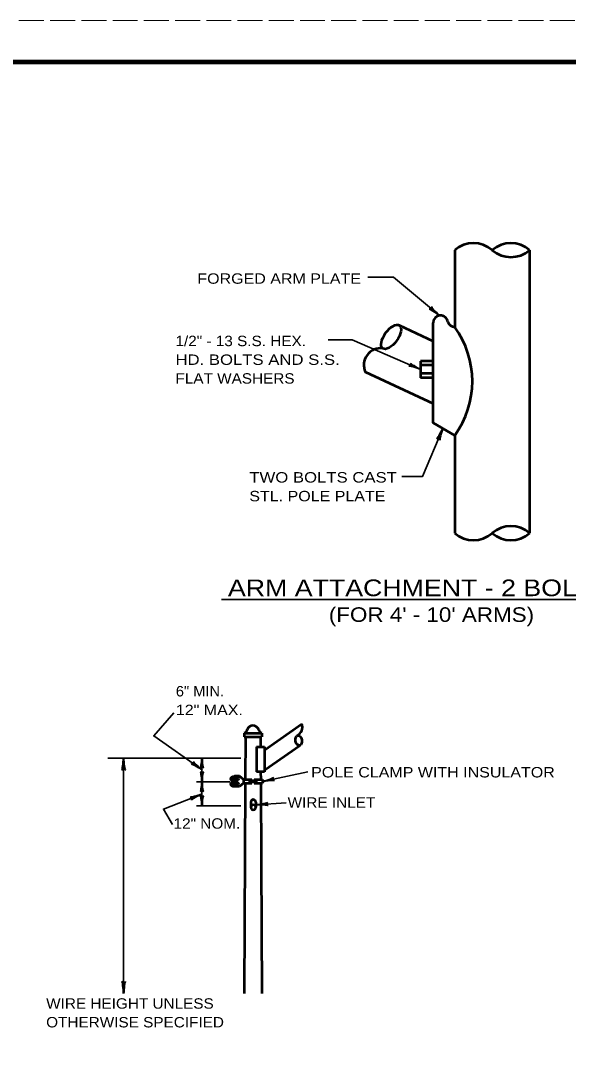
# Model space of a CAD drawing. Extents: x -1 to 679, y -228 to 440.
# Drawn here: x 224.4 to 356, y 192.8 to 440.2 of the extents above; entities that cross this region are included whole.
import ezdxf
from ezdxf.enums import TextEntityAlignment as Align

# ---------------------------------------------------------------- set-up
doc = ezdxf.new("R2010")
doc.units = 0
doc.linetypes.add('LONG_DASHED', pattern=[7.5, 6, -1.5])
doc.layers.add('1', color=7, linetype='Continuous', lineweight=35)
doc.layers.add('61', color=7, linetype='Continuous', lineweight=35)

msp = doc.modelspace()

# ---------------------------------------------------------------- hatches: boundary and pattern name
at = {"layer": '1'}
h = msp.add_hatch(color=256, dxfattribs=at)
edge = h.paths.add_edge_path()
edge.add_ellipse((275.808, 258.088), major_axis=(0.907, 0), ratio=0.6666667, start_angle=0, end_angle=360)
h = msp.add_hatch(color=256, dxfattribs=at)
edge = h.paths.add_edge_path()
edge.add_ellipse((275.808, 256.835), major_axis=(0.907, 0), ratio=0.6666667, start_angle=0, end_angle=360)

# ---------------------------------------------------------------- linework, layer by layer
at = {"layer": '1', "lineweight": 53}
for p, q in [((328.678, 385.1), (328.678, 366.6)), ((346.678, 385.1), (346.678, 317.1)), ((323.561, 363.183), (315.404, 366.986)), ((323.482, 358.445), (320.482, 358.445)), ((320.482, 358.445), (320.482, 354.445)), ((323.482, 357.445), (320.482, 357.445)), ((323.561, 348.183), (307.247, 355.79)), ((323.482, 355.445), (320.482, 355.445)), ((323.482, 354.445), (320.482, 354.445)), ((328.678, 340.6), (328.678, 317.1)), ((283.035, 265.061), (291.955, 271.301)), ((278.1, 269.095), (282.32, 269.095)), ((278.1, 269.095), (278.1, 268.195)), ((278.1, 268.195), (282.32, 268.195)), ((278.4, 268.195), (278.34, 257.915)), ((282.02, 268.195), (282.04, 265.775)), ((282.32, 269.095), (282.32, 268.195)), ((281.11, 265.775), (283.01, 265.775)), ((281.11, 265.775), (281.11, 259.735)), ((283.01, 265.775), (283.01, 259.735)), ((283.035, 260.221), (291.475, 266.121)), ((277.02, 258.695), (275.8, 258.695)), ((277.94, 257.915), (277.02, 258.695)), ((277.94, 257.915), (279.92, 257.915)), ((277.94, 257.915), (277.94, 257.015)), ((279.42, 257.915), (279.42, 257.015)), ((279.92, 257.915), (279.92, 257.015)), ((280.52, 257.915), (282.48, 257.915)), ((280.52, 257.915), (280.52, 257.015)), ((281, 257.915), (281, 257.015)), ((283.01, 259.735), (281.11, 259.735)), ((282.06, 259.735), (282.08, 257.915)), ((282.48, 257.915), (282.48, 257.015)), ((277.02, 256.235), (275.8, 256.235)), ((277.94, 257.015), (277.02, 256.235)), ((277.94, 257.015), (279.92, 257.015)), ((278.34, 257.015), (278.1, 206.515)), ((280.52, 257.015), (282.48, 257.015)), ((282.08, 257.015), (282.168, 237.955)), ((279.68, 252.455), (279.7, 251.255)), ((280.9, 252.475), (280.9, 251.255)), ((282.18, 237.955), (282.32, 206.515))]:
    msp.add_line(p, q, dxfattribs=at)
at = {"layer": '1'}
for p, q in [((272.629, 301.175), (367.649, 301.175)), ((245.329, 263.089), (277.329, 263.089)), ((249.145, 263.089), (249.145, 206.515)), ((267.971, 257.404), (267.971, 263.089)), ((282.509, 257.449), (293.413, 259.808)), ((266.657, 257.404), (274.657, 257.404)), ((267.971, 257.404), (267.971, 251.593)), ((280.94, 251.88), (288.21, 252.352)), ((266.657, 251.593), (277.329, 251.593))]:
    msp.add_line(p, q, dxfattribs=at)
for points in [[(325.01, 369.374), (313.992, 378.629), (307.832, 378.629)], [(320.482, 356.445), (304.054, 363.511), (298.304, 363.511)], [(325.826, 342.247), (320.974, 330.729), (315.963, 330.729)], [(268.019, 260.256), (256.395, 268.416), (261.221, 273.923)], [(267.951, 254.408), (258.706, 250.804), (260.882, 247.133)]]:
    msp.add_lwpolyline(points, dxfattribs=at)
at = {"layer": '1', "lineweight": 53}
msp.add_lwpolyline([(328.678, 340.6), (323.482, 343.6), (323.482, 367.6)], dxfattribs=at)
for centre, radius, start, end in [((333.178, 379.861), 6.907, 49.34186, 130.65814), ((342.178, 379.861), 6.907, 49.34186, 130.65814), ((342.178, 390.332), 6.907, 229.34186, 310.65814), ((325.269, 367.606), 1.787, 7.93348, 180.19616), ((328.793, 368.449), 1.852, 198.77174, 266.46102), ((310.949, 353.6), 21.985, 323.74899, 36.25101), ((310.874, 357.511), 4.015, 82.46091, 205.39139), ((333.178, 322.34), 6.907, 229.34186, 310.65814), ((342.178, 311.869), 6.907, 49.34186, 130.65814), ((342.178, 322.34), 6.907, 229.34186, 310.65814), ((277.902, 270.019), 0.936, 281.94387, 347.91984), ((280.213, 269.418), 1.453, 16.19781, 163.80219), ((282.523, 270.019), 0.936, 192.08016, 258.05613), ((289.835, 270.525), 2.264, 295.32486, 20.09191), ((280.289, 252.478), 0.605, 358.85054, 181.71286), ((280.295, 251.269), 0.605, 358.85054, 181.71286), ((280.295, 251.232), 0.605, 178.28714, 1.14946)]:
    msp.add_arc(centre, radius, start, end, dxfattribs=at)
at = {"layer": '1', "lineweight": 40}
for centre, major_axis, ratio, start_param, end_param in [((324.288, 370.257), (-1.232, 1.264), 0.07063, 6.2823074, 8.5597026), ((324.288, 370.257), (-1.232, 1.264), 0.07063, 6.2823074, 8.5597026), ((323.997, 369.865), (1.468, -1.029), 0.122415, 0.8963533, 3.1415927), ((323.997, 369.865), (1.468, -1.029), 0.122415, 0.8963533, 3.1415927), ((319.371, 356.622), (1.702, -0.562), 0.122415, 0.8963533, 3.1415927), ((319.371, 356.622), (1.702, -0.562), 0.122415, 0.8963533, 3.1415927), ((319.536, 357.082), (1.544, -0.855), 0.07063, 3.1407148, 5.41811), ((319.536, 357.082), (1.544, -0.855), 0.07063, 3.1407148, 5.41811), ((325.196, 341.297), (-0.844, -1.55), 0.07063, 6.2823074, 8.5597026), ((325.196, 341.297), (-0.844, -1.55), 0.07063, 6.2823074, 8.5597026), ((325.657, 341.134), (0.549, 1.706), 0.122415, 0.8963533, 3.1415927), ((325.657, 341.134), (0.549, 1.706), 0.122415, 0.8963533, 3.1415927), ((248.933, 261.968), (0.176, 1.756), 0.07063, 3.1407148, 5.41811), ((249.421, 261.998), (-0.156, 1.786), 0.122415, 0.8963533, 3.1415927), ((267.763, 261.959), (0.176, 1.756), 0.07063, 4.6265008, 5.41811), ((268.251, 261.989), (-0.156, 1.786), 0.122415, 0.8963533, 1.6612166), ((266.967, 260.657), (1.551, -0.898), 0.122415, 0.8963533, 3.1415927), ((266.967, 260.657), (1.551, -0.898), 0.122415, 0.8963533, 3.1415927), ((267.223, 261.073), (-1.337, 1.153), 0.07063, 6.2823074, 8.5597026), ((267.223, 261.073), (-1.337, 1.153), 0.07063, 6.2823074, 8.5597026), ((267.82, 262.451), (0.176, 1.756), 0.07063, 3.1407148, 4.3375003), ((267.82, 258.043), (0.176, -1.756), 0.07063, 1.9456851, 3.1424706), ((268.191, 262.498), (-0.156, 1.786), 0.122415, 1.9568509, 3.1415927), ((268.191, 257.995), (-0.156, -1.786), 0.122415, 3.1415927, 4.3263344), ((267.763, 258.534), (0.176, -1.756), 0.07063, 0.8650754, 1.6566845), ((267.763, 256.275), (0.176, 1.756), 0.07063, 4.6265008, 5.41811), ((268.251, 258.505), (-0.156, -1.786), 0.122415, 4.6219687, 5.386832), ((268.251, 256.304), (-0.156, 1.786), 0.122415, 0.8963533, 1.6612166), ((283.517, 257.95), (-1.712, -0.53), 0.122415, 0.8963533, 3.1415927), ((283.517, 257.95), (-1.712, -0.53), 0.122415, 0.8963533, 3.1415927), ((283.649, 257.479), (1.754, 0.2), 0.07063, 6.2823074, 8.5597026), ((283.649, 257.479), (1.754, 0.2), 0.07063, 6.2823074, 8.5597026), ((267.82, 256.766), (0.176, 1.756), 0.07063, 3.1407148, 4.3375003), ((268.191, 256.814), (-0.156, 1.786), 0.122415, 1.9568509, 3.1415927), ((266.83, 254.199), (-1.7, -0.474), 0.07063, 6.2823074, 8.5597026), ((267.035, 253.755), (1.607, 0.794), 0.122415, 0.8963533, 3.1415927), ((267.82, 252.231), (0.176, -1.756), 0.07063, 1.9456851, 3.1424706), ((267.763, 252.723), (0.176, -1.756), 0.07063, 0.8650754, 1.6566845), ((268.251, 252.693), (-0.156, -1.786), 0.122415, 4.6219687, 5.386832), ((268.191, 252.184), (-0.156, -1.786), 0.122415, 3.1415927, 4.3263344), ((282.01, 252.227), (-1.772, -0.272), 0.122415, 0.8963533, 3.1415927), ((282.071, 251.742), (-1.764, 0.061), 0.07063, 3.1407148, 5.41811), ((248.869, 207.606), (0.156, -1.786), 0.122415, 0.8963533, 3.1415927), ((248.869, 207.606), (0.156, -1.786), 0.122415, 0.8963533, 3.1415927), ((249.357, 207.636), (-0.176, -1.756), 0.07063, 3.1407148, 5.41811), ((249.357, 207.636), (-0.176, -1.756), 0.07063, 3.1407148, 5.41811)]:
    msp.add_ellipse(centre, major_axis=major_axis, ratio=ratio, start_param=start_param, end_param=end_param, dxfattribs=at)
at = {"layer": '1', "lineweight": 53}
for centre, major_axis, ratio in [((313.402, 364.239), (-2.002, -2.748), 0.476726), ((291.195, 267.314), (-0.27, 1.196), 0.618585), ((275.808, 258.088), (0.907, 0), 0.666667), ((275.808, 256.835), (0.907, 0), 0.666667)]:
    msp.add_ellipse(centre, major_axis=major_axis, ratio=ratio, dxfattribs=at)
at = {"layer": '61', "linetype": 'LONG_DASHED', "lineweight": 13}
msp.add_line((-0.979, 440.237), (679.041, 440.237), dxfattribs=at)
at = {"layer": '61', "lineweight": 158}
msp.add_lwpolyline([(668.061, 430.237), (29.021, 430.237), (29.021, 10.217)], dxfattribs=at)

# ---------------------------------------------------------------- texts
at = {"layer": '1'}
for s, height, width, p in [('FORGED ARM PLATE', 2.5, 1.15, (266.864, 377.017)), ('1/2" - 13 S.S. HEX.', 2.5, 1.1, (261.607, 362.028)), ('HD. BOLTS AND S.S.', 2.5, 1.2, (261.607, 357.528)), ('FLAT WASHERS', 2.5, 1.1, (261.607, 353.028)), ('TWO BOLTS CAST', 2.5, 1.2, (279.348, 329.262)), ('STL. POLE PLATE', 2.5, 1.15, (279.348, 324.762)), ("(FOR 4' - 10' ARMS)", 3.5, 1.15, (298.44, 295.789)), ('6" MIN.', 2.5, 1.05, (261.697, 277.883)), ('12" MAX.', 2.5, 1.15, (261.697, 273.383)), ('POLE CLAMP WITH INSULATOR', 2.5, 1.15, (294.189, 258.42)), ('WIRE INLET', 2.5, 1.1, (288.547, 251.144)), ('12" NOM.', 2.5, 1.1, (261.153, 246.113)), ('WIRE HEIGHT UNLESS', 2.5, 1.1, (230.548, 202.869)), ('OTHERWISE SPECIFIED', 2.5, 1.1, (230.548, 198.369))]:
    msp.add_text(s, height=height, dxfattribs=dict(at, width=width)).set_placement(p)
at = {"layer": '1', "width": 1.2}
msp.add_text('ARM ATTACHMENT - 2 BOLTS', height=4, dxfattribs=at).set_placement((320.218, 301.968), align=Align.CENTER)

doc.saveas('drawing.dxf')
